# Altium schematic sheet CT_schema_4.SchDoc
size 461 x 227 mm
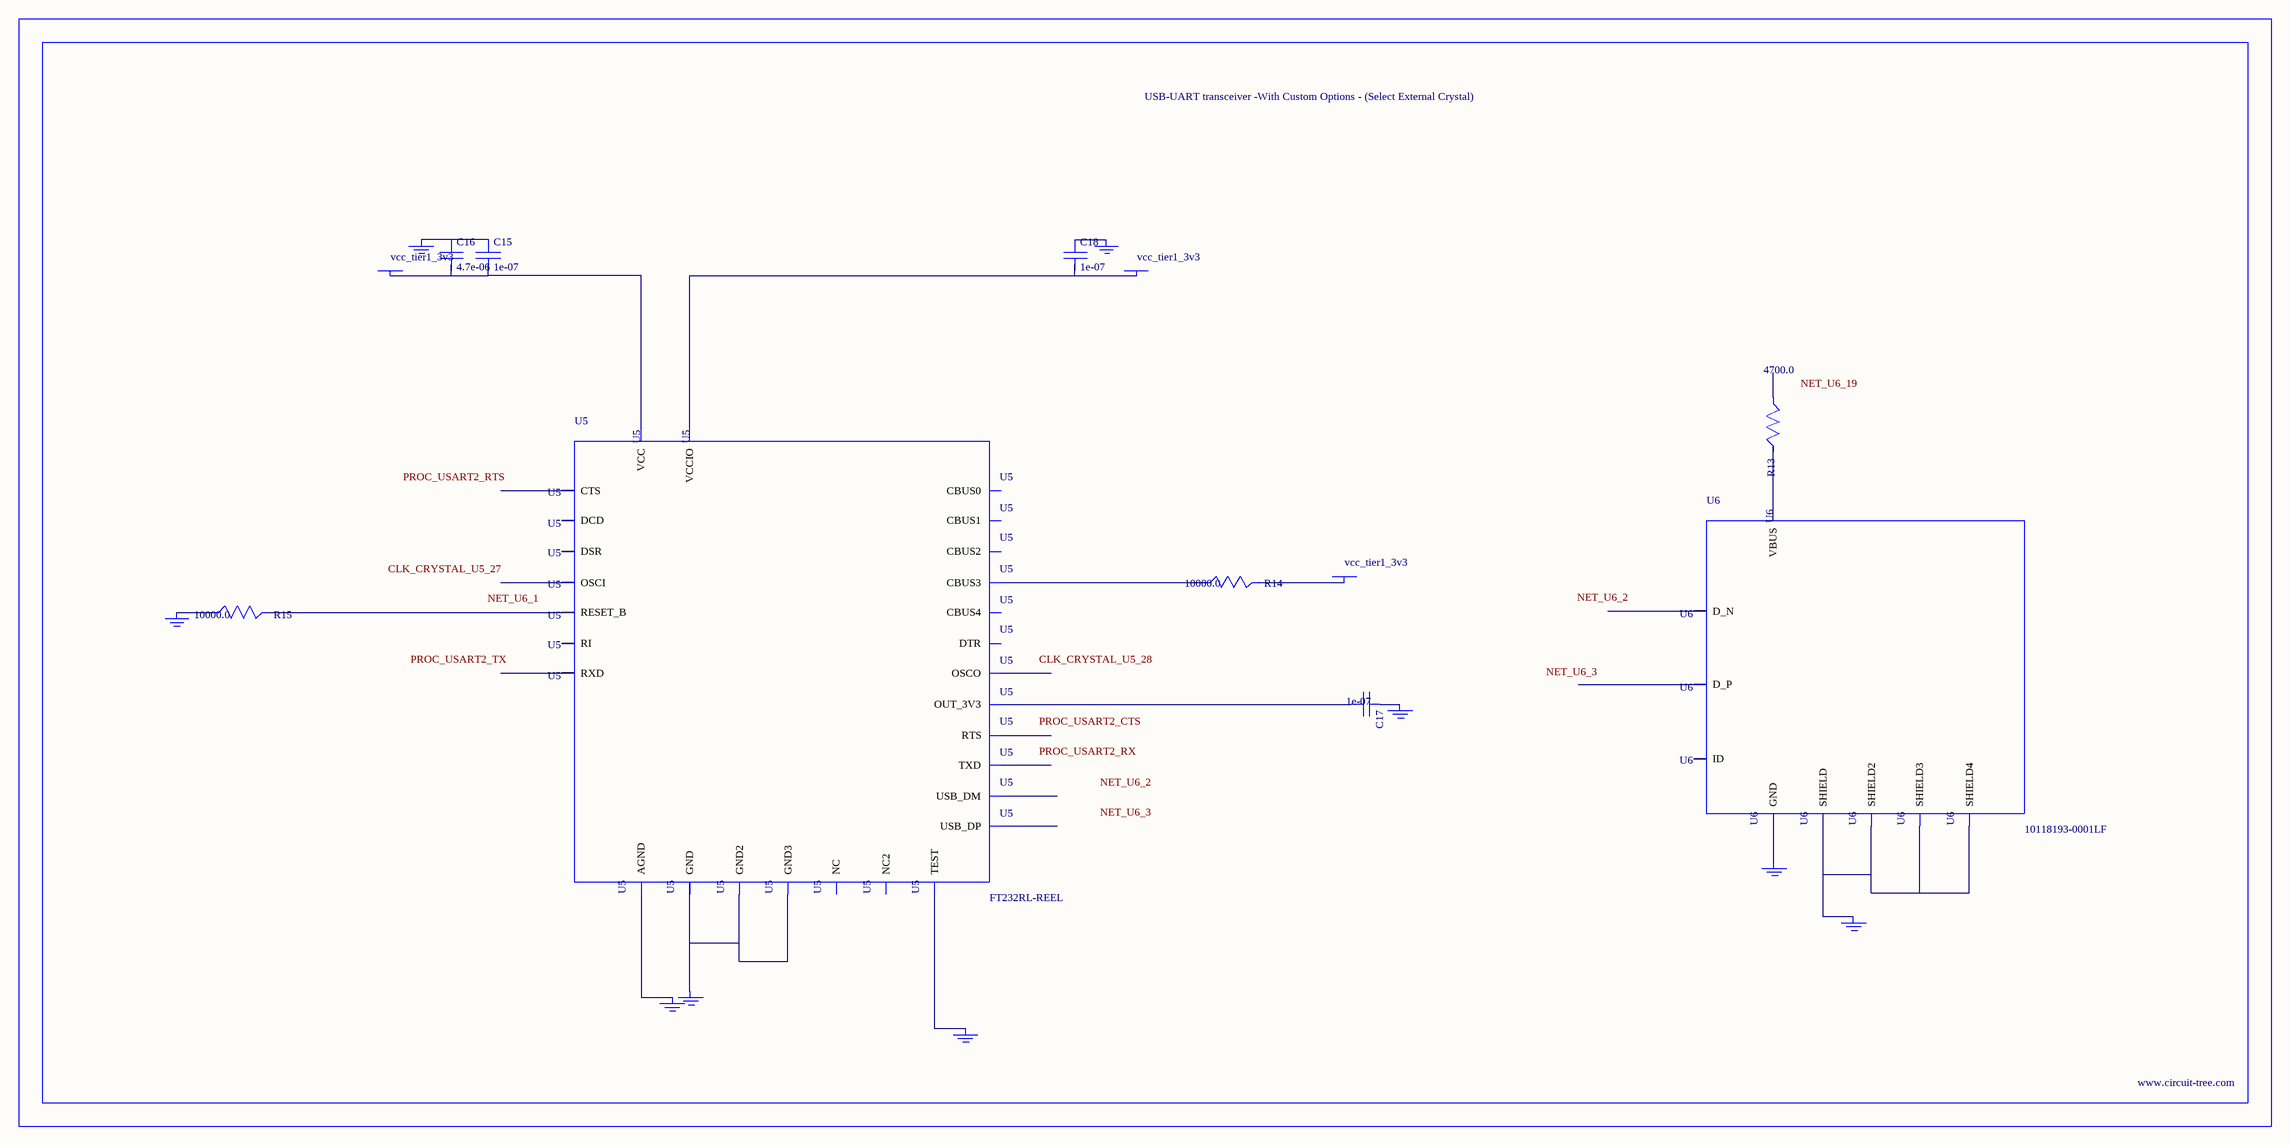
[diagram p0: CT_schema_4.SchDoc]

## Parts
BORDER3  (no value)
C15  1e-07  [C0402]
C16  4.7e-06  [C0805]
C17  1e-07  [C0402]
C18  1e-07  [C0402]
GND_INSTANCE_3_0  (no value)
GND_INSTANCE_3_1  (no value)
GND_INSTANCE_3_2  (no value)
GND_INSTANCE_3_3  (no value)
GND_INSTANCE_3_4  (no value)
GND_INSTANCE_3_5  (no value)
GND_INSTANCE_3_6  (no value)
GND_INSTANCE_3_7  (no value)
GND_INSTANCE_3_8  (no value)
POWER_INSTANCE_3_0  vcc_tier1_3v3
POWER_INSTANCE_3_1  vcc_tier1_3v3
POWER_INSTANCE_3_2  vcc_tier1_3v3
R13  4700.0  [R0603]
R14  10000.0  [R0603]
R15  10000.0  [R0603]
U5  FT232RL-REEL  [SSOP-28]
U6  10118193-0001LF  [FCI_10118193-0001LF]

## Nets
NetC15_1: C15.1 C16.1 GND_INSTANCE_3_3.0(GND)
NetC15_2: C15.2 C16.2 POWER_INSTANCE_3_2.0(PWR) U5.20(VCC)
NetC17_1: C17.1 GND_INSTANCE_3_1.0(GND)
NetC17_2: C17.2 U5.17(OUT_3V3)
NetC18_1: C18.1 GND_INSTANCE_3_0.0(GND)
NetC18_2: C18.2 POWER_INSTANCE_3_0.0(PWR) U5.4(VCCIO)
NetGND_INSTANCE_3_2_0: GND_INSTANCE_3_2.0(GND) R15.1
NetGND_INSTANCE_3_4_0: GND_INSTANCE_3_4.0(GND) U5.25(AGND)
NetGND_INSTANCE_3_5_0: GND_INSTANCE_3_5.0(GND) U5.26(TEST)
NetGND_INSTANCE_3_6_0: GND_INSTANCE_3_6.0(GND) U5.7(GND) U5.18(GND2) U5.21(GND3)
NetGND_INSTANCE_3_7_0: GND_INSTANCE_3_7.0(GND) U6.6(SHIELD) U6.7(SHIELD2) U6.8(SHIELD3) U6.9(SHIELD4)
NetGND_INSTANCE_3_8_0: GND_INSTANCE_3_8.0(GND) U6.5(GND)
NetPOWER_INSTANCE_3_1_0: POWER_INSTANCE_3_1.0(PWR) R14.2
NetR13_2: R13.2 U6.1(VBUS)
NetR14_1: R14.1 U5.14(CBUS3)
NetR15_2: R15.2 U5.19(RESET_B)

Not connected (* = marked no-connect by the designer): R13 1; U5 1(TXD) 2(DTR) 3(RTS) 5(RXD) 6(RI) 8(NC) 9(DSR) 10(DCD) 11(CTS) 12(CBUS4) 13(CBUS2) 15(USB_DP) 16(USB_DM) 22(CBUS1) 23(CBUS0) 24(NC2) 27(OSCI) 28(OSCO); U6 2(D_N) 3(D_P) 4(ID)

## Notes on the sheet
- Labels drawn without touching a wire or pin: CLK_CRYSTAL_U5_27, CLK_CRYSTAL_U5_28, NET_U6_1, NET_U6_2, NET_U6_3, NET_U6_19, PROC_USART2_CTS, PROC_USART2_RTS, PROC_USART2_RX, PROC_USART2_TX

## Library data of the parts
BORDER3 = BORDER_PAGE3
C15 C17 C18 = C0402C104K3RACTU
C16 = C0805C475K4RACTU
GND_INSTANCE_3_0-GND_INSTANCE_3_8 = GND
POWER_INSTANCE_3_0-POWER_INSTANCE_3_2 = PWR
R13 = RC0603JR-074K7L
R14 R15 = RC0603JR-0710KL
